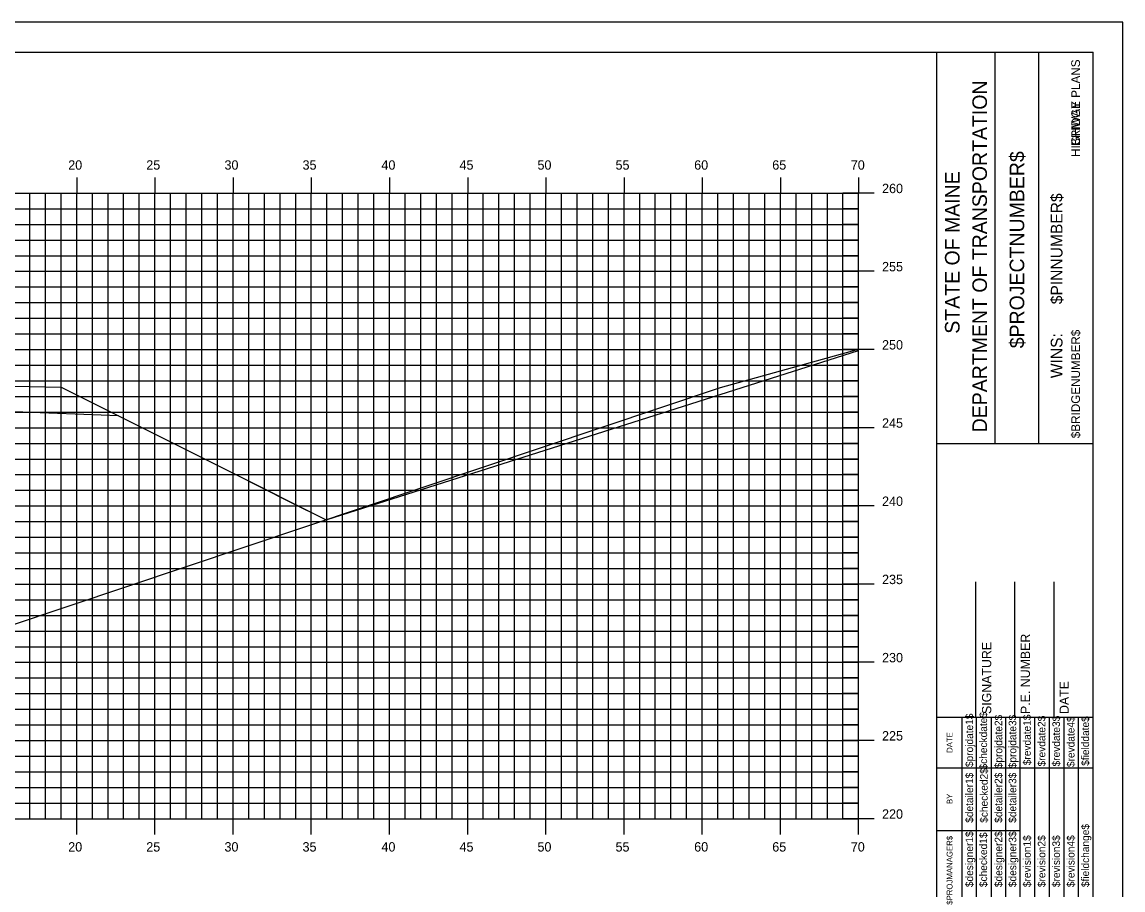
# Model space of a CAD drawing. Extents: x 1168600 to 1177589, y 610178 to 611246.
# Drawn here: x 1174536.6 to 1174607, y 610955 to 611010.5 of the extents above; entities that cross this region are included whole.
import ezdxf

# ---------------------------------------------------------------- set-up
doc = ezdxf.new("R2010")
doc.units = 0
for name, color, linetype in [('_Construction', 7, 'Continuous'), ('_Station Equation', 7, 'Continuous'), ('BORDER', 7, 'Continuous'), ('D_Roadway_SubGrade', 7, 'Continuous'), ('D_Slope_Direction', 7, 'Continuous'), ('D_Text_Standard', 7, 'Continuous'), ('H_V ANNOTATION', 7, 'Continuous'), ('MAJOR', 7, 'Continuous'), ('MINOR', 7, 'Continuous')]:
    doc.layers.add(name, color=color, linetype=linetype)

msp = doc.modelspace()

# ---------------------------------------------------------------- linework, layer by layer
at = {"layer": '_Construction'}
for p, q in [((1174605.124, 611008.596), (1174445.124, 611008.596)), ((1174595.124, 610903.599), (1174595.124, 611008.599)), ((1174598.852, 610983.593), (1174598.852, 611008.593)), ((1174601.647, 610983.593), (1174601.647, 611008.593)), ((1174605.124, 610903.599), (1174605.124, 611008.599)), ((1174595.125, 610983.59), (1174605.124, 610983.59)), ((1174597.624, 610966.099), (1174597.624, 610974.747)), ((1174600.124, 610966.099), (1174600.124, 610974.747)), ((1174602.624, 610966.099), (1174602.624, 610974.747)), ((1174595.124, 610966.099), (1174605.124, 610966.099))]:
    msp.add_line(p, q, dxfattribs=at)
msp.add_lwpolyline([(1174437.03, 610900.537), (1174607.03, 610900.537), (1174607.03, 611010.537), (1174437.03, 611010.537)], close=True, dxfattribs=at)
for points in [[(1174596.739, 610962.849), (1174596.739, 610966.099)], [(1174597.671, 610948.602), (1174597.671, 610966.099)], [(1174598.603, 610966.099), (1174598.603, 610948.602)], [(1174599.535, 610948.602), (1174599.535, 610966.099)], [(1174600.466, 610948.602), (1174600.466, 610966.099)], [(1174601.398, 610948.602), (1174601.398, 610966.099)], [(1174602.33, 610948.602), (1174602.33, 610966.099)], [(1174603.261, 610948.602), (1174603.261, 610966.099)], [(1174604.193, 610948.602), (1174604.193, 610966.099)], [(1174596.74, 610948.602), (1174596.74, 610965.393)], [(1174595.124, 610962.849), (1174605.124, 610962.849)], [(1174595.124, 610958.849), (1174596.74, 610958.849)], [(1174596.739, 610958.849), (1174600.465, 610958.849)]]:
    msp.add_lwpolyline(points, dxfattribs=at)
at = {"layer": '_Station Equation'}
for points in [[(1174450.124, 610990.702), (1174455.424, 610988.219), (1174466.897, 610982.867), (1174471.499, 610980.747), (1174499.564, 610969.293), (1174503.046, 610969.381), (1174517.821, 610970.24), (1174524.497, 610970.464), (1174535.767, 610971.901), (1174581.293, 610987.165), (1174590.124, 610989.615)], [(1174536.124, 610987.243), (1174539.124, 610987.183), (1174542.787, 610985.351), (1174550.207, 610981.642), (1174553.718, 610979.886), (1174556.071, 610978.709), (1174556.072, 610978.709), (1174556.122, 610978.726), (1174556.137, 610978.731), (1174590.124, 610989.534)]]:
    msp.add_lwpolyline(points, dxfattribs=at)
at = {"layer": 'D_Roadway_SubGrade'}
msp.add_lwpolyline([(1174536.124, 610987.243), (1174539.124, 610987.183), (1174542.787, 610985.351), (1174536.124, 610985.618)], close=True, dxfattribs=at)
at = {"layer": 'D_Slope_Direction'}
for points in [[(1174539.124, 610987.183), (1174550.207, 610981.642)], [(1174550.207, 610981.642), (1174556.072, 610978.709)]]:
    msp.add_lwpolyline(points, dxfattribs=at)
at = {"layer": 'D_Text_Standard'}
msp.add_lwpolyline([(1174479.313, 610977.558), (1174490.041, 610982.922), (1174498.448, 610987.125), (1174501.124, 610988.463), (1174504.124, 610988.523), (1174520.124, 610987.883), (1174536.124, 610987.243), (1174539.124, 610987.183), (1174542.787, 610985.351), (1174550.207, 610981.642), (1174556.072, 610978.709)], dxfattribs=at)
at = {"layer": 'MAJOR'}
for p, q in [((1174540.124, 611000.598), (1174540.124, 610999.596)), ((1174545.124, 611000.598), (1174545.124, 610999.596)), ((1174550.124, 611000.598), (1174550.124, 610999.596)), ((1174555.124, 611000.598), (1174555.124, 610999.596)), ((1174560.124, 611000.598), (1174560.124, 610999.596)), ((1174565.124, 611000.598), (1174565.124, 610999.596)), ((1174570.124, 611000.598), (1174570.124, 610999.596)), ((1174575.124, 611000.598), (1174575.124, 610999.596)), ((1174580.124, 611000.598), (1174580.124, 610999.596)), ((1174585.124, 611000.598), (1174585.124, 610999.596)), ((1174590.124, 611000.598), (1174590.124, 610999.596)), ((1174450.124, 610999.596), (1174590.124, 610999.596)), ((1174450.124, 610999.596), (1174590.124, 610999.596)), ((1174540.124, 610959.596), (1174540.124, 610999.596)), ((1174545.124, 610959.596), (1174545.124, 610999.596)), ((1174550.124, 610959.596), (1174550.124, 610999.596)), ((1174555.124, 610959.596), (1174555.124, 610999.596)), ((1174560.124, 610959.596), (1174560.124, 610999.596)), ((1174565.124, 610959.596), (1174565.124, 610999.596)), ((1174570.124, 610959.596), (1174570.124, 610999.596)), ((1174575.124, 610959.596), (1174575.124, 610999.596)), ((1174580.124, 610959.596), (1174580.124, 610999.596)), ((1174585.124, 610959.596), (1174585.124, 610999.596)), ((1174591.126, 610999.596), (1174589.122, 610999.596)), ((1174590.124, 610959.596), (1174590.124, 610999.596)), ((1174590.124, 610959.596), (1174590.124, 610999.596)), ((1174450.124, 610994.596), (1174590.124, 610994.596)), ((1174591.126, 610994.596), (1174589.122, 610994.596)), ((1174450.124, 610989.596), (1174590.124, 610989.596)), ((1174591.126, 610989.596), (1174589.122, 610989.596)), ((1174450.124, 610984.596), (1174590.124, 610984.596)), ((1174591.126, 610984.596), (1174589.122, 610984.596)), ((1174450.124, 610979.596), (1174590.124, 610979.596)), ((1174591.126, 610979.596), (1174589.122, 610979.596)), ((1174450.124, 610974.596), (1174590.124, 610974.596)), ((1174591.126, 610974.596), (1174589.122, 610974.596)), ((1174450.124, 610969.596), (1174590.124, 610969.596)), ((1174591.126, 610969.596), (1174589.122, 610969.596)), ((1174450.124, 610964.596), (1174590.124, 610964.596)), ((1174591.126, 610964.596), (1174589.122, 610964.596)), ((1174450.124, 610959.596), (1174590.124, 610959.596)), ((1174450.124, 610959.596), (1174590.124, 610959.596)), ((1174540.124, 610958.594), (1174540.124, 610959.596)), ((1174545.124, 610958.594), (1174545.124, 610959.596)), ((1174550.124, 610958.594), (1174550.124, 610959.596)), ((1174555.124, 610958.594), (1174555.124, 610959.596)), ((1174560.124, 610958.594), (1174560.124, 610959.596)), ((1174565.124, 610958.594), (1174565.124, 610959.596)), ((1174570.124, 610958.594), (1174570.124, 610959.596)), ((1174575.124, 610958.594), (1174575.124, 610959.596)), ((1174580.124, 610958.594), (1174580.124, 610959.596)), ((1174585.124, 610958.594), (1174585.124, 610959.596)), ((1174591.126, 610959.596), (1174589.122, 610959.596)), ((1174590.124, 610958.594), (1174590.124, 610959.596))]:
    msp.add_line(p, q, dxfattribs=at)
at = {"layer": 'MINOR'}
for p, q in [((1174537.124, 610959.596), (1174537.124, 610999.596)), ((1174538.124, 610959.596), (1174538.124, 610999.596)), ((1174539.124, 610959.596), (1174539.124, 610999.596)), ((1174541.124, 610959.596), (1174541.124, 610999.596)), ((1174542.124, 610959.596), (1174542.124, 610999.596)), ((1174543.124, 610959.596), (1174543.124, 610999.596)), ((1174544.124, 610959.596), (1174544.124, 610999.596)), ((1174546.124, 610959.596), (1174546.124, 610999.596)), ((1174547.124, 610959.596), (1174547.124, 610999.596)), ((1174548.124, 610959.596), (1174548.124, 610999.596)), ((1174549.124, 610959.596), (1174549.124, 610999.596)), ((1174551.124, 610959.596), (1174551.124, 610999.596)), ((1174552.124, 610959.596), (1174552.124, 610999.596)), ((1174553.124, 610959.596), (1174553.124, 610999.596)), ((1174554.124, 610959.596), (1174554.124, 610999.596)), ((1174556.124, 610959.596), (1174556.124, 610999.596)), ((1174557.124, 610959.596), (1174557.124, 610999.596)), ((1174558.124, 610959.596), (1174558.124, 610999.596)), ((1174559.124, 610959.596), (1174559.124, 610999.596)), ((1174561.124, 610959.596), (1174561.124, 610999.596)), ((1174562.124, 610959.596), (1174562.124, 610999.596)), ((1174563.124, 610959.596), (1174563.124, 610999.596)), ((1174564.124, 610959.596), (1174564.124, 610999.596)), ((1174566.124, 610959.596), (1174566.124, 610999.596)), ((1174567.124, 610959.596), (1174567.124, 610999.596)), ((1174568.124, 610959.596), (1174568.124, 610999.596)), ((1174569.124, 610959.596), (1174569.124, 610999.596)), ((1174571.124, 610959.596), (1174571.124, 610999.596)), ((1174572.124, 610959.596), (1174572.124, 610999.596)), ((1174573.124, 610959.596), (1174573.124, 610999.596)), ((1174574.124, 610959.596), (1174574.124, 610999.596)), ((1174576.124, 610959.596), (1174576.124, 610999.596)), ((1174577.124, 610959.596), (1174577.124, 610999.596)), ((1174578.124, 610959.596), (1174578.124, 610999.596)), ((1174579.124, 610959.596), (1174579.124, 610999.596)), ((1174581.124, 610959.596), (1174581.124, 610999.596)), ((1174582.124, 610959.596), (1174582.124, 610999.596)), ((1174583.124, 610959.596), (1174583.124, 610999.596)), ((1174584.124, 610959.596), (1174584.124, 610999.596)), ((1174586.124, 610959.596), (1174586.124, 610999.596)), ((1174587.124, 610959.596), (1174587.124, 610999.596)), ((1174588.124, 610959.596), (1174588.124, 610999.596)), ((1174589.124, 610959.596), (1174589.124, 610999.596)), ((1174450.124, 610998.596), (1174590.124, 610998.596)), ((1174590.124, 610998.596), (1174589.122, 610998.596)), ((1174450.124, 610997.596), (1174590.124, 610997.596)), ((1174590.124, 610997.596), (1174589.122, 610997.596)), ((1174450.124, 610996.596), (1174590.124, 610996.596)), ((1174590.124, 610996.596), (1174589.122, 610996.596)), ((1174450.124, 610995.596), (1174590.124, 610995.596)), ((1174590.124, 610995.596), (1174589.122, 610995.596)), ((1174450.124, 610993.596), (1174590.124, 610993.596)), ((1174590.124, 610993.596), (1174589.122, 610993.596)), ((1174450.124, 610992.596), (1174590.124, 610992.596)), ((1174590.124, 610992.596), (1174589.122, 610992.596)), ((1174450.124, 610991.596), (1174590.124, 610991.596)), ((1174590.124, 610991.596), (1174589.122, 610991.596)), ((1174450.124, 610990.596), (1174590.124, 610990.596)), ((1174590.124, 610990.596), (1174589.122, 610990.596)), ((1174450.124, 610988.596), (1174590.124, 610988.596)), ((1174590.124, 610988.596), (1174589.122, 610988.596)), ((1174450.124, 610987.596), (1174590.124, 610987.596)), ((1174590.124, 610987.596), (1174589.122, 610987.596)), ((1174450.124, 610986.596), (1174590.124, 610986.596)), ((1174590.124, 610986.596), (1174589.122, 610986.596)), ((1174450.124, 610985.596), (1174590.124, 610985.596)), ((1174590.124, 610985.596), (1174589.122, 610985.596)), ((1174450.124, 610983.596), (1174590.124, 610983.596)), ((1174590.124, 610983.596), (1174589.122, 610983.596)), ((1174450.124, 610982.596), (1174590.124, 610982.596)), ((1174590.124, 610982.596), (1174589.122, 610982.596)), ((1174450.124, 610981.596), (1174590.124, 610981.596)), ((1174590.124, 610981.596), (1174589.122, 610981.596)), ((1174450.124, 610980.596), (1174590.124, 610980.596)), ((1174590.124, 610980.596), (1174589.122, 610980.596)), ((1174450.124, 610978.596), (1174590.124, 610978.596)), ((1174590.124, 610978.596), (1174589.122, 610978.596)), ((1174450.124, 610977.596), (1174590.124, 610977.596)), ((1174590.124, 610977.596), (1174589.122, 610977.596)), ((1174450.124, 610976.596), (1174590.124, 610976.596)), ((1174590.124, 610976.596), (1174589.122, 610976.596)), ((1174450.124, 610975.596), (1174590.124, 610975.596)), ((1174590.124, 610975.596), (1174589.122, 610975.596)), ((1174450.124, 610973.596), (1174590.124, 610973.596)), ((1174590.124, 610973.596), (1174589.122, 610973.596)), ((1174450.124, 610972.596), (1174590.124, 610972.596)), ((1174590.124, 610972.596), (1174589.122, 610972.596)), ((1174450.124, 610971.596), (1174590.124, 610971.596)), ((1174590.124, 610971.596), (1174589.122, 610971.596)), ((1174450.124, 610970.596), (1174590.124, 610970.596)), ((1174590.124, 610970.596), (1174589.122, 610970.596)), ((1174450.124, 610968.596), (1174590.124, 610968.596)), ((1174590.124, 610968.596), (1174589.122, 610968.596)), ((1174450.124, 610967.596), (1174590.124, 610967.596)), ((1174590.124, 610967.596), (1174589.122, 610967.596)), ((1174450.124, 610966.596), (1174590.124, 610966.596)), ((1174590.124, 610966.596), (1174589.122, 610966.596)), ((1174450.124, 610965.596), (1174590.124, 610965.596)), ((1174590.124, 610965.596), (1174589.122, 610965.596)), ((1174450.124, 610963.596), (1174590.124, 610963.596)), ((1174590.124, 610963.596), (1174589.122, 610963.596)), ((1174450.124, 610962.596), (1174590.124, 610962.596)), ((1174590.124, 610962.596), (1174589.122, 610962.596)), ((1174450.124, 610961.596), (1174590.124, 610961.596)), ((1174590.124, 610961.596), (1174589.122, 610961.596)), ((1174450.124, 610960.596), (1174590.124, 610960.596)), ((1174590.124, 610960.596), (1174589.122, 610960.596))]:
    msp.add_line(p, q, dxfattribs=at)

# ---------------------------------------------------------------- texts
at = {"layer": '_Construction'}
for s, height, p in [('BRIDGE PLANS', 0.55901, (1174604.282, 611002.62)), ('HIGHWAY PLANS', 0.55901, (1174604.282, 611001.911)), ('DEPARTMENT OF TRANSPORTATION', 0.93176, (1174598.331, 610984.302)), ('$PROJECTNUMBER$', 0.93176, (1174600.716, 610989.675)), ('STATE OF MAINE', 0.93176, (1174596.579, 610990.608)), ('$PINNUMBER$', 0.74527, (1174603.161, 610992.493)), ('$BRIDGENUMBER$', 0.55901, (1174604.282, 610983.926)), ('P.E. NUMBER', 0.59055, (1174601.085, 610966.291)), ('SIGNATURE', 0.5906, (1174598.604, 610966.291)), ('DATE', 0.5906, (1174603.565, 610966.291)), ('$projdate1$', 0.48455, (1174597.447, 610962.899)), ('$checkdate$', 0.48455, (1174598.341, 610962.742)), ('$projdate2$', 0.48455, (1174599.31, 610962.821)), ('$projdate3$', 0.48455, (1174600.205, 610962.821)), ('$revdate1$', 0.4845, (1174601.136, 610963.017)), ('$revdate2$', 0.4845, (1174602.068, 610962.939)), ('$revdate3$', 0.4845, (1174603, 610962.939)), ('$revdate4$', 0.4845, (1174603.931, 610962.899)), ('$fielddate$', 0.48455, (1174604.863, 610962.978)), ('DATE', 0.3714, (1174596.128, 610963.805)), ('$detailer1$', 0.48455, (1174597.447, 610959.334)), ('$checked2$', 0.4845, (1174598.378, 610959.334)), ('$detailer2$', 0.48455, (1174599.31, 610959.334)), ('$detailer3$', 0.48455, (1174600.205, 610959.334)), ('BY', 0.3714, (1174596.128, 610960.534)), ('$fieldchange$', 0.48455, (1174604.863, 610955.222)), ('$PROJMANAGER$', 0.37275, (1174596.128, 610954.094)), ('$designer1$', 0.48455, (1174597.447, 610955.222)), ('$checked1$', 0.4845, (1174598.341, 610955.222)), ('$designer2$', 0.48455, (1174599.31, 610955.222)), ('$designer3$', 0.48455, (1174600.205, 610955.222)), ('$revision1$', 0.48455, (1174601.136, 610955.222)), ('$revision2$', 0.48455, (1174602.068, 610955.222)), ('$revision3$', 0.48455, (1174603, 610955.222)), ('$revision4$', 0.48455, (1174603.931, 610955.222))]:
    msp.add_text(s, height=height, rotation=90, dxfattribs=at).set_placement(p)
at = {"layer": 'BORDER'}
msp.add_text('WINS:', height=0.7453, rotation=90, dxfattribs=at).set_placement((1174603.159, 610987.764))
at = {"layer": 'H_V ANNOTATION'}
for s, p in [('20', (1174539.578, 611001.096)), ('25', (1174544.57, 611001.096)), ('30', (1174549.572, 611001.096)), ('35', (1174554.564, 611001.096)), ('40', (1174559.61, 611001.096)), ('45', (1174564.602, 611001.096)), ('50', (1174569.588, 611001.096)), ('55', (1174574.58, 611001.096)), ('60', (1174579.61, 611001.096)), ('65', (1174584.602, 611001.096)), ('70', (1174589.626, 611001.096)), ('260', (1174591.624, 610999.596)), ('255', (1174591.624, 610994.596)), ('250', (1174591.624, 610989.596)), ('245', (1174591.624, 610984.596)), ('240', (1174591.624, 610979.596)), ('235', (1174591.624, 610974.596)), ('230', (1174591.624, 610969.596)), ('225', (1174591.624, 610964.596)), ('220', (1174591.624, 610959.596)), ('20', (1174539.578, 610957.496)), ('25', (1174544.57, 610957.496)), ('30', (1174549.572, 610957.496)), ('35', (1174554.564, 610957.496)), ('40', (1174559.61, 610957.496)), ('45', (1174564.602, 610957.496)), ('50', (1174569.588, 610957.496)), ('55', (1174574.58, 610957.496)), ('60', (1174579.61, 610957.496)), ('65', (1174584.602, 610957.496)), ('70', (1174589.626, 610957.496))]:
    msp.add_text(s, height=0.6, dxfattribs=at).set_placement(p)

doc.saveas('drawing.dxf')
